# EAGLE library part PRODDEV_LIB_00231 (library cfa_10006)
CFAG12864I
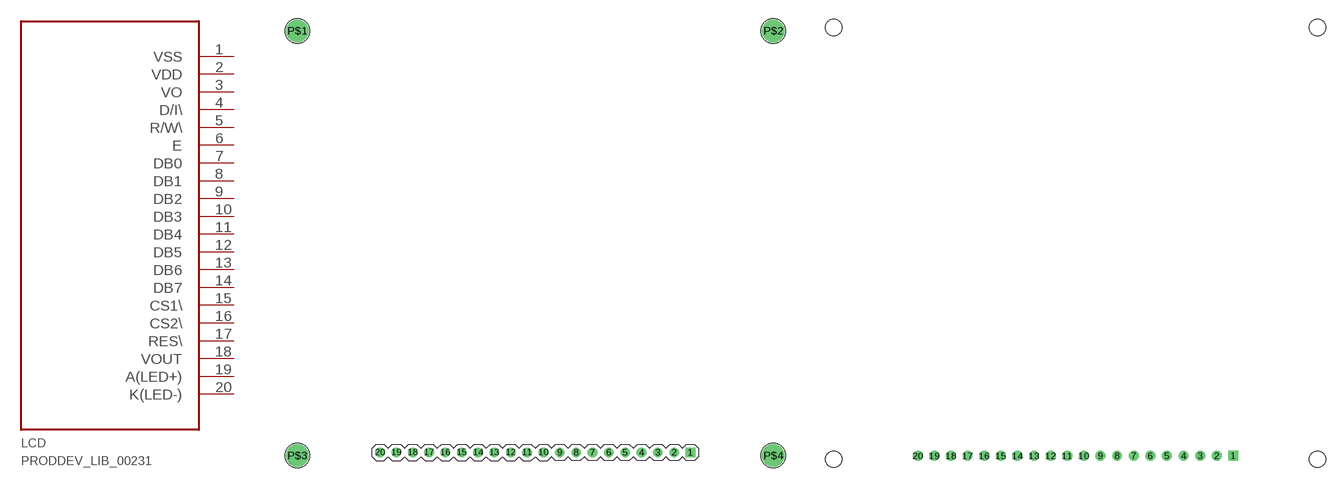
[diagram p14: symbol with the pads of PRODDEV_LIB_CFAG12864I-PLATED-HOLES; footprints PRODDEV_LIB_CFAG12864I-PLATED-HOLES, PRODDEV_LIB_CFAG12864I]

Designator prefix LCD

## PRODDEV_LIB_00231  [PRODDEV_LIB_CFAG12864I-PLATED-HOLES]
1  VSS  pwr
2  VDD  pwr
3  VO  pas
4  D/I\  in
5  R/W\  in
6  E  in
7  DB0  in
8  DB1
9  DB2
10  DB3
11  DB4
12  DB5
13  DB6
14  DB7
15  CS1\  in
16  CS2\  in
17  RES\  in
18  VOUT  pas
19  A(LED+)  pas
20  K(LED-)  pas

## PRODDEV_LIB_00231NON-PLATED-HOLES  [PRODDEV_LIB_CFAG12864I]
Pads as for PRODDEV_LIB_CFAG12864I-PLATED-HOLES

## Footprint PRODDEV_LIB_CFAG12864I-PLATED-HOLES (pad centres in mm)
drill 1 square: 1 0,0
drill 1 round: 2 -2.54,0; 3 -5.08,0; 4 -7.62,0; 5 -10.16,0; 6 -12.7,0; 7 -15.24,0; 8 -17.78,0; 9 -20.32,0; 10 -22.86,0; 11 -25.4,0; 12 -27.94,0; 13 -30.48,0; 14 -33.02,0; 15 -35.56,0; 16 -38.1,0; 17 -40.64,0; 18 -43.18,0; 19 -45.72,0; 20 -48.26,0
drill 2.5 round: P$1 -61.13,65.5; P$2 12.87,65.5; P$3 -61.13,-0.5; P$4 12.87,-0.5

## Footprint PRODDEV_LIB_CFAG12864I (pad centres in mm)
drill 1 square: 1 0,0
drill 1 round: 2 -2.54,0; 3 -5.08,0; 4 -7.62,0; 5 -10.16,0; 6 -12.7,0; 7 -15.24,0; 8 -17.78,0; 9 -20.32,0; 10 -22.86,0; 11 -25.4,0; 12 -27.94,0; 13 -30.48,0; 14 -33.02,0; 15 -35.56,0; 16 -38.1,0; 17 -40.64,0; 18 -43.18,0; 19 -45.72,0; 20 -48.26,0
hole 2.5 at -61.13,65.5
hole 2.5 at 12.87,65.5
hole 2.5 at -61.13,-0.5
hole 2.5 at 12.87,-0.5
